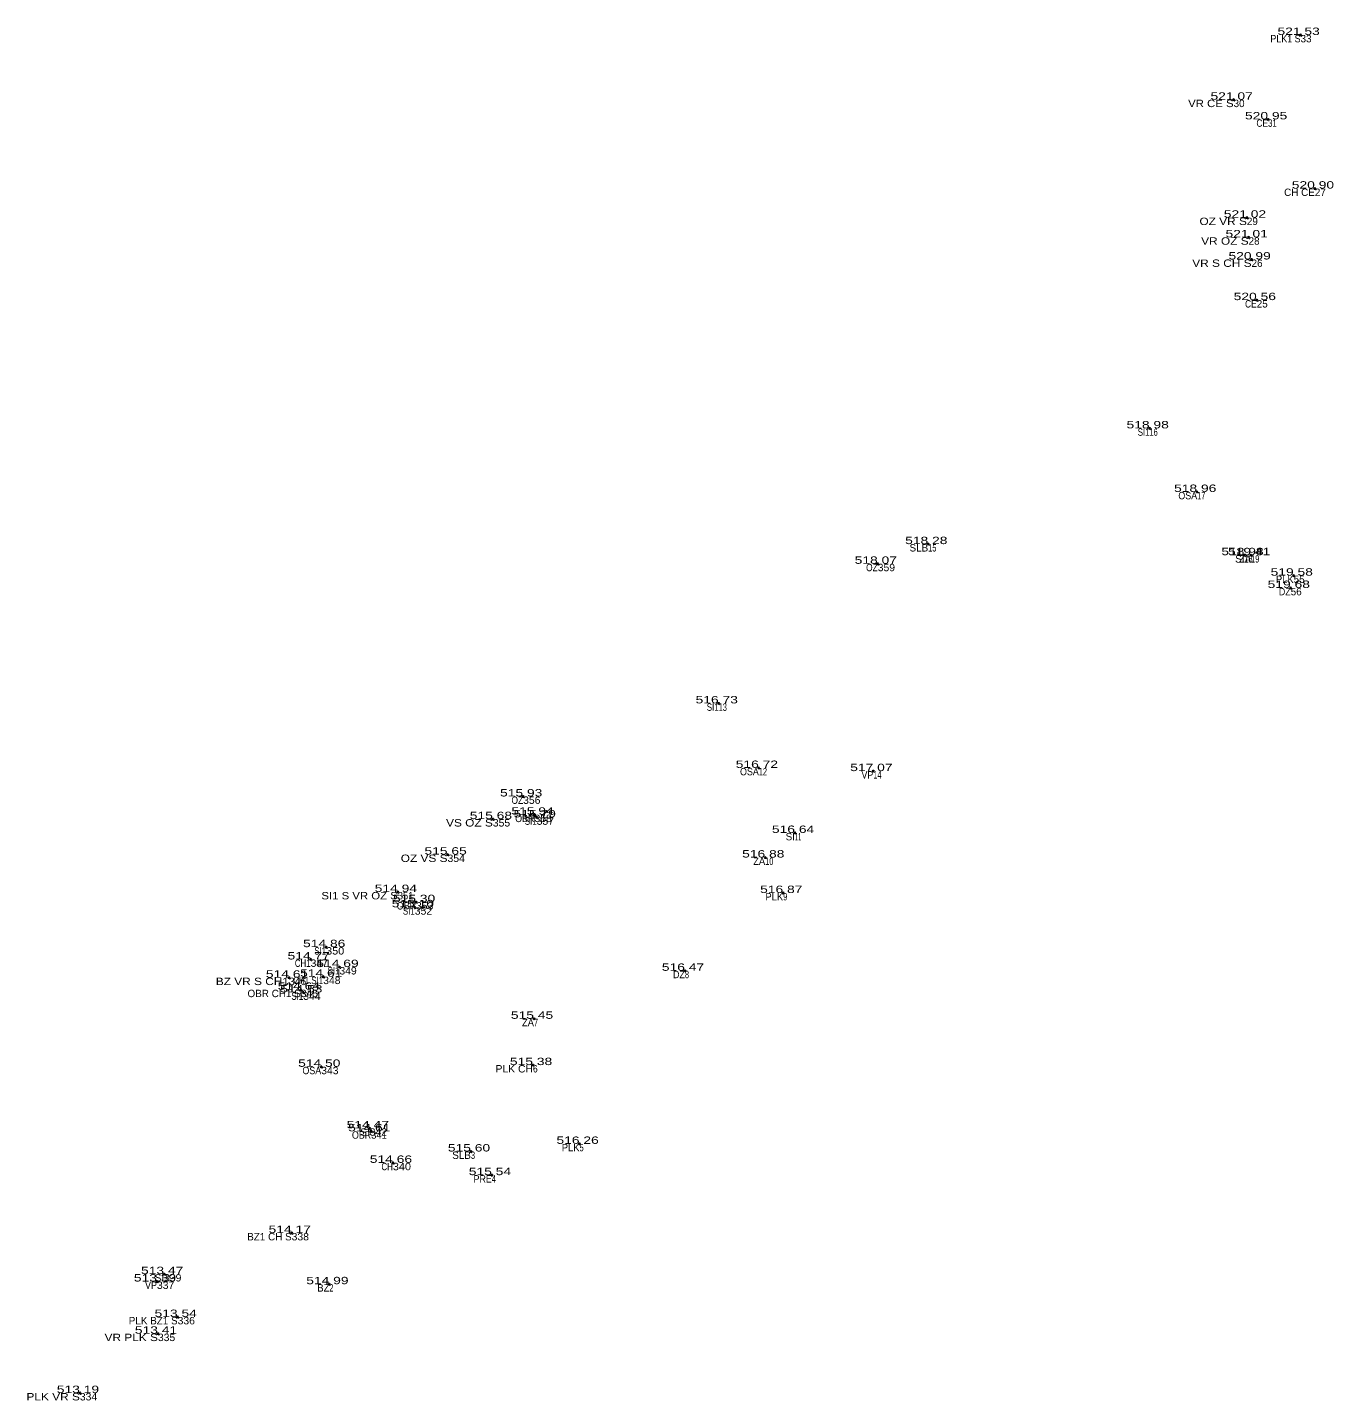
# Model space of a CAD drawing. Extents: x -643086 to -639283, y -1131805 to -1123269.
# Drawn here: x -641374.9 to -641321.9, y -1126035.7 to -1125979.9 of the extents above; entities that cross this region are included whole.
import ezdxf
from ezdxf.enums import TextEntityAlignment as Align

# ---------------------------------------------------------------- set-up
doc = ezdxf.new("R2010")
doc.units = 0
doc.header["$LTSCALE"] = 0.12
doc.header["$PDMODE"] = 32
doc.header["$PDSIZE"] = 0.06
for name, color, linetype in [('1', 7, 'Continuous'), ('2', 7, 'Continuous'), ('3', 7, 'Continuous'), ('4', 7, 'Continuous')]:
    doc.layers.add(name, color=color, linetype=linetype)

msp = doc.modelspace()

# ---------------------------------------------------------------- linework, layer by layer
at = {"layer": '1'}
for p in [(-641323.21, -1125980.25), (-641325.93, -1125982.88), (-641324.53, -1125983.68), (-641322.63, -1125986.49), (-641325.39, -1125987.67), (-641325.32, -1125988.47), (-641325.2, -1125989.37), (-641324.99, -1125991.02), (-641329.34, -1125996.23), (-641327.41, -1125998.81), (-641338.33, -1126000.93), (-641340.38, -1126001.73), (-641325.49, -1126001.38), (-641325.22, -1126001.38), (-641323.49, -1126002.21), (-641323.61, -1126002.71), (-641346.84, -1126007.4), (-641345.21, -1126010.02), (-641340.56, -1126010.15), (-641354.78, -1126011.18), (-641354.32, -1126011.92), (-641356.01, -1126012.1), (-641354.23, -1126012.03), (-641343.74, -1126012.66), (-641357.85, -1126013.54), (-641344.95, -1126013.66), (-641359.87, -1126015.06), (-641344.22, -1126015.1), (-641359.18, -1126015.68), (-641359.13, -1126015.47), (-641362.78, -1126017.3), (-641363.41, -1126017.8), (-641364.29, -1126018.54), (-641362.9, -1126018.5), (-641362.24, -1126018.11), (-641348.21, -1126018.26), (-641363.81, -1126019.03), (-641363.71, -1126019.14), (-641354.34, -1126020.21), (-641362.98, -1126022.16), (-641354.38, -1126022.09), (-641361.01, -1126024.66), (-641360.95, -1126024.78), (-641352.49, -1126025.29), (-641356.9, -1126025.6), (-641360.07, -1126026.06), (-641356.05, -1126026.56), (-641364.18, -1126028.91), (-641369.65, -1126030.88), (-641369.36, -1126030.58), (-641362.65, -1126030.99), (-641368.81, -1126032.32), (-641369.61, -1126033), (-641372.78, -1126035.41)]:
    msp.add_point(p, dxfattribs=at)

# ---------------------------------------------------------------- texts
at = {"layer": '2'}
for s, p in [('33', (-641323.21, -1125980.55)), ('30', (-641325.93, -1125983.18)), ('27', (-641322.63, -1125986.79)), ('29', (-641325.39, -1125987.97)), ('28', (-641325.32, -1125988.77)), ('26', (-641325.2, -1125989.67)), ('25', (-641324.99, -1125991.32)), ('55', (-641323.49, -1126002.51)), ('56', (-641323.61, -1126003.01))]:
    msp.add_text(s, height=0.3, dxfattribs=at).set_placement(p)
for s, width, p in [('31', 0.8, (-641324.53, -1125983.98)), ('16', 0.65, (-641329.34, -1125996.53)), ('17', 0.6, (-641327.41, -1125999.11)), ('15', 0.6, (-641338.33, -1126001.23)), ('359', 1.05, (-641340.38, -1126002.03)), ('18', 0.6, (-641325.49, -1126001.68)), ('19', 0.6, (-641325.22, -1126001.68)), ('13', 0.6, (-641346.84, -1126007.7)), ('12', 0.6, (-641345.21, -1126010.32)), ('14', 0.6, (-641340.56, -1126010.45)), ('356', 1.05, (-641354.78, -1126011.48)), ('358', 1.05, (-641354.32, -1126012.22)), ('355', 1.05, (-641356.01, -1126012.4)), ('357', 1.05, (-641354.23, -1126012.33)), ('11', 0.45, (-641343.74, -1126012.96)), ('354', 1.05, (-641357.85, -1126013.84)), ('10', 0.65, (-641344.95, -1126013.96)), ('351', 0.95, (-641359.87, -1126015.36)), ('9', 0.75, (-641344.22, -1126015.4)), ('352', 1.05, (-641359.18, -1126015.98)), ('353', 1.05, (-641359.13, -1126015.77)), ('350', 1.1, (-641362.78, -1126017.6)), ('347', 1.05, (-641363.41, -1126018.1)), ('346', 1.05, (-641364.29, -1126018.84)), ('348', 1.05, (-641362.9, -1126018.8)), ('349', 1.05, (-641362.24, -1126018.41)), ('8', 0.75, (-641348.21, -1126018.56)), ('345', 1.05, (-641363.81, -1126019.33)), ('344', 1.05, (-641363.71, -1126019.44)), ('7', 0.75, (-641354.34, -1126020.51)), ('343', 1.05, (-641362.98, -1126022.46)), ('6', 0.85, (-641354.38, -1126022.39)), ('342', 1.05, (-641361.01, -1126024.96)), ('341', 0.95, (-641360.95, -1126025.08)), ('5', 0.75, (-641352.49, -1126025.59)), ('3', 0.75, (-641356.9, -1126025.9)), ('340', 1.1, (-641360.07, -1126026.36)), ('4', 0.75, (-641356.05, -1126026.86)), ('338', 1.05, (-641364.18, -1126029.21)), ('337', 1.05, (-641369.65, -1126031.18)), ('339', 1.05, (-641369.36, -1126030.88)), ('2', 0.75, (-641362.65, -1126031.29)), ('336', 1.05, (-641368.81, -1126032.62)), ('335', 1.05, (-641369.61, -1126033.3)), ('334', 1.05, (-641372.78, -1126035.71))]:
    msp.add_text(s, height=0.3, dxfattribs=dict(at, width=width)).set_placement(p)
at = {"layer": '3', "width": 1.4}
for s, p in [('521 53 ', (-641323.21, -1125980.25)), ('521 07 ', (-641325.93, -1125982.88)), ('520 95 ', (-641324.53, -1125983.68)), ('520 90 ', (-641322.63, -1125986.49)), ('521 02 ', (-641325.39, -1125987.67)), ('521 01 ', (-641325.32, -1125988.47)), ('520 99 ', (-641325.2, -1125989.37)), ('520 56 ', (-641324.99, -1125991.02)), ('518 98 ', (-641329.34, -1125996.23)), ('518 96 ', (-641327.41, -1125998.81)), ('518 28 ', (-641338.33, -1126000.93)), ('518 98 ', (-641325.49, -1126001.38)), ('519 41 ', (-641325.22, -1126001.38)), ('518 07 ', (-641340.38, -1126001.73)), ('519 68 ', (-641323.61, -1126002.71)), ('519 58 ', (-641323.49, -1126002.21)), ('516 73 ', (-641346.84, -1126007.4)), ('516 72 ', (-641345.21, -1126010.02)), ('517 07 ', (-641340.56, -1126010.15)), ('515 93 ', (-641354.78, -1126011.18)), ('515 68 ', (-641356.01, -1126012.1)), ('515 94 ', (-641354.32, -1126011.92)), ('515 79 ', (-641354.23, -1126012.03)), ('516 64 ', (-641343.74, -1126012.66)), ('515 65 ', (-641357.85, -1126013.54)), ('516 88 ', (-641344.95, -1126013.66)), ('514 94 ', (-641359.87, -1126015.06)), ('515 30 ', (-641359.13, -1126015.47)), ('516 87 ', (-641344.22, -1126015.1)), ('515 10 ', (-641359.18, -1126015.68)), ('514 86 ', (-641362.78, -1126017.3)), ('514 77 ', (-641363.41, -1126017.8)), ('514 69 ', (-641362.24, -1126018.11)), ('516 47 ', (-641348.21, -1126018.26)), ('514 61 ', (-641364.29, -1126018.54)), ('514 61 ', (-641362.9, -1126018.5)), ('514 64 ', (-641363.81, -1126019.03)), ('514 53 ', (-641363.71, -1126019.14)), ('515 45 ', (-641354.34, -1126020.21)), ('514 50 ', (-641362.98, -1126022.16)), ('515 38 ', (-641354.38, -1126022.09)), ('514 47 ', (-641361.01, -1126024.66)), ('514 61 ', (-641360.95, -1126024.78)), ('515 60 ', (-641356.9, -1126025.6)), ('516 26 ', (-641352.49, -1126025.29)), ('514 66 ', (-641360.07, -1126026.06)), ('515 54 ', (-641356.05, -1126026.56)), ('514 17 ', (-641364.18, -1126028.91)), ('513 47 ', (-641369.36, -1126030.58)), ('513 39 ', (-641369.65, -1126030.88)), ('514 99 ', (-641362.65, -1126030.99)), ('513 54 ', (-641368.81, -1126032.32)), ('513 41 ', (-641369.61, -1126033)), ('513 19 ', (-641372.78, -1126035.41))]:
    msp.add_text(s, height=0.3, dxfattribs=at).set_placement(p, align=Align.CENTER)
at = {"layer": '4'}
for s, width, p in [('PLK1 S', 0.9, (-641323.21, -1125980.55)), ('VR CE S', 1.15, (-641325.93, -1125983.18)), ('CE', 0.85, (-641324.53, -1125983.98)), ('OZ VR S', 1.2, (-641325.39, -1125987.97)), ('VR OZ S', 1.2, (-641325.32, -1125988.77)), ('VR S CH S', 1.2, (-641325.2, -1125989.67)), ('CE', 0.85, (-641324.99, -1125991.32)), ('SI1', 0.8, (-641329.34, -1125996.53)), ('OSA', 0.9, (-641327.41, -1125999.11)), ('OZ', 0.85, (-641340.38, -1126002.03)), ('ZA', 0.95, (-641325.22, -1126001.68)), ('PLK', 0.95, (-641323.49, -1126002.51)), ('DZ', 0.9, (-641323.61, -1126003.01)), ('SI1', 0.8, (-641346.84, -1126007.7)), ('OSA', 0.9, (-641345.21, -1126010.32)), ('VP', 0.9, (-641340.56, -1126010.45)), ('OZ', 0.85, (-641354.78, -1126011.48)), ('OBR', 0.9, (-641354.32, -1126012.22)), ('VS OZ S', 1.2, (-641356.01, -1126012.4)), ('SI1', 0.8, (-641354.23, -1126012.33)), ('OZ VS S', 1.2, (-641357.85, -1126013.84)), ('ZA', 0.95, (-641344.95, -1126013.96)), ('SI1 S VR OZ S', 1.15, (-641359.87, -1126015.36)), ('PLK', 0.95, (-641344.22, -1126015.4)), ('OBR', 0.9, (-641359.13, -1126015.77)), ('SI1', 0.8, (-641359.18, -1126015.98)), ('SI1', 0.8, (-641362.78, -1126017.6)), ('CH1', 0.8, (-641363.41, -1126018.1)), ('BZ VR S CH1', 1.2, (-641364.29, -1126018.84)), ('CH1 SI1', 0.8, (-641362.9, -1126018.8)), ('SI1', 0.8, (-641362.24, -1126018.41)), ('DZ', 0.9, (-641348.21, -1126018.56)), ('SI1', 0.8, (-641363.71, -1126019.44)), ('ZA', 0.95, (-641354.34, -1126020.51)), ('OSA', 0.9, (-641362.98, -1126022.46)), ('PLK CH', 1.05, (-641354.38, -1126022.39)), ('OBR', 0.9, (-641360.95, -1126025.08)), ('PLK', 0.95, (-641352.49, -1126025.59)), ('CH', 0.8, (-641360.07, -1126026.36)), ('PRE', 0.9, (-641356.05, -1126026.86)), ('VP', 0.9, (-641369.65, -1126031.18)), ('BZ', 0.95, (-641362.65, -1126031.29)), ('VR PLK S', 1.2, (-641369.61, -1126033.3)), ('PLK VR S', 1.2, (-641372.78, -1126035.71))]:
    msp.add_text(s, height=0.3, dxfattribs=dict(at, width=width)).set_placement(p, align=Align.RIGHT)
for s, p in [('CH CE', (-641322.63, -1125986.79)), ('SLB', (-641338.33, -1126001.23)), ('SI', (-641325.49, -1126001.68)), ('SI', (-641343.74, -1126012.96)), ('OBR CH1 S', (-641363.81, -1126019.33)), ('SI', (-641361.01, -1126024.96)), ('SLB', (-641356.9, -1126025.9)), ('BZ1 CH S', (-641364.18, -1126029.21)), ('SI', (-641369.36, -1126030.88)), ('PLK BZ1 S', (-641368.81, -1126032.62))]:
    msp.add_text(s, height=0.3, dxfattribs=at).set_placement(p, align=Align.RIGHT)

doc.saveas('drawing.dxf')
